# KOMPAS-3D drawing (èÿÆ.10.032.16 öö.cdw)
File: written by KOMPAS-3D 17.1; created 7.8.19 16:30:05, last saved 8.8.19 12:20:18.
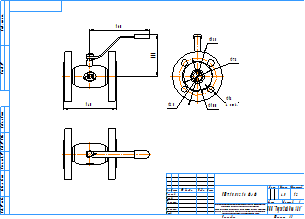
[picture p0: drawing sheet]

Sheet 1: A3, landscape

Title block, sheet 1: name: КШТ.10.032.16 Ф/Ф; material: Сталь 20  ГОСТ 1050-2013; mass: 4,5; sheets: 1; sheet format: A3; stored path: C:\Users\kka\KOMPAS_Work\Модели кранов для исследований\DN65\КШТ.10.065.16 СС.cdw

Views: Вид 1, Проекционный вид 2, Проекционный вид 3
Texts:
  kka
  adl
  Рама для чертежей
  Лит-Масса-Масштаб
  Материал-Предприятие
  Масштаб
  Изм.
  Лист
  № докум.
  Подп.
  Дата
  Лит.
  Разраб.
  Пров.
  Т.контр.
  Листов
  Внимание! Данный продукт является объектом авторского права ООО «Торговый Дом АДЛ».
  Запрещается изменение, копирование, распространение
  (в том числе путем копирования на другие сайты и ресурсы в Интернете)
  или любое иное использование информации и объектов без предварительного
  согласия правообладателя (ООО «Торговый Дом АДЛ»).
  Н.контр.
  Утв.
  ООО "Торговый дом АДЛ"
  Изменение
  Номер документа
  Подпись
  Обозначение документа
  Наименование изделия
  Масса изделия по ГОСТ 2.109-73
  Порядковый номер листа
  Общее количество листов в документе
  Характер работы, выполненной лицом, подписавшим документ
  Наименование или индекс предприятия, выпускающего документ
  Инв. № подл.
  Подп. и дата
  Взам. инв. №
  Инв. № дубл.
  Инвентарный номер подлинника по ГОСТ 2.501-68
  Подпись принявшего подлинник в отдел технической документации
  Инвентарный номер подлинника, взамен которого выпущен данный подлинник
  Инвентарный номер дубликата по ГОСТ 2.502-68
  Подпись принявшего дубликат в отдел технической документации
  Справ. №
  Перв. примен.
  Обозначение документа, взамен или на основании которого выпущен данный документ
  Обозначение документа, в котором впервые записан данный документ
  Подпись лица, копировавшего чертеж
  Обозначение формата листа
  !Рама для чертежа
Dimensions and other numbers on the sheet: 111; 160; 140; 25; 100; 135; 78; 18; 4 отв.; 1:2; 1; 4,5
